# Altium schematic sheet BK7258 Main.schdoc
size 562 x 302 mm
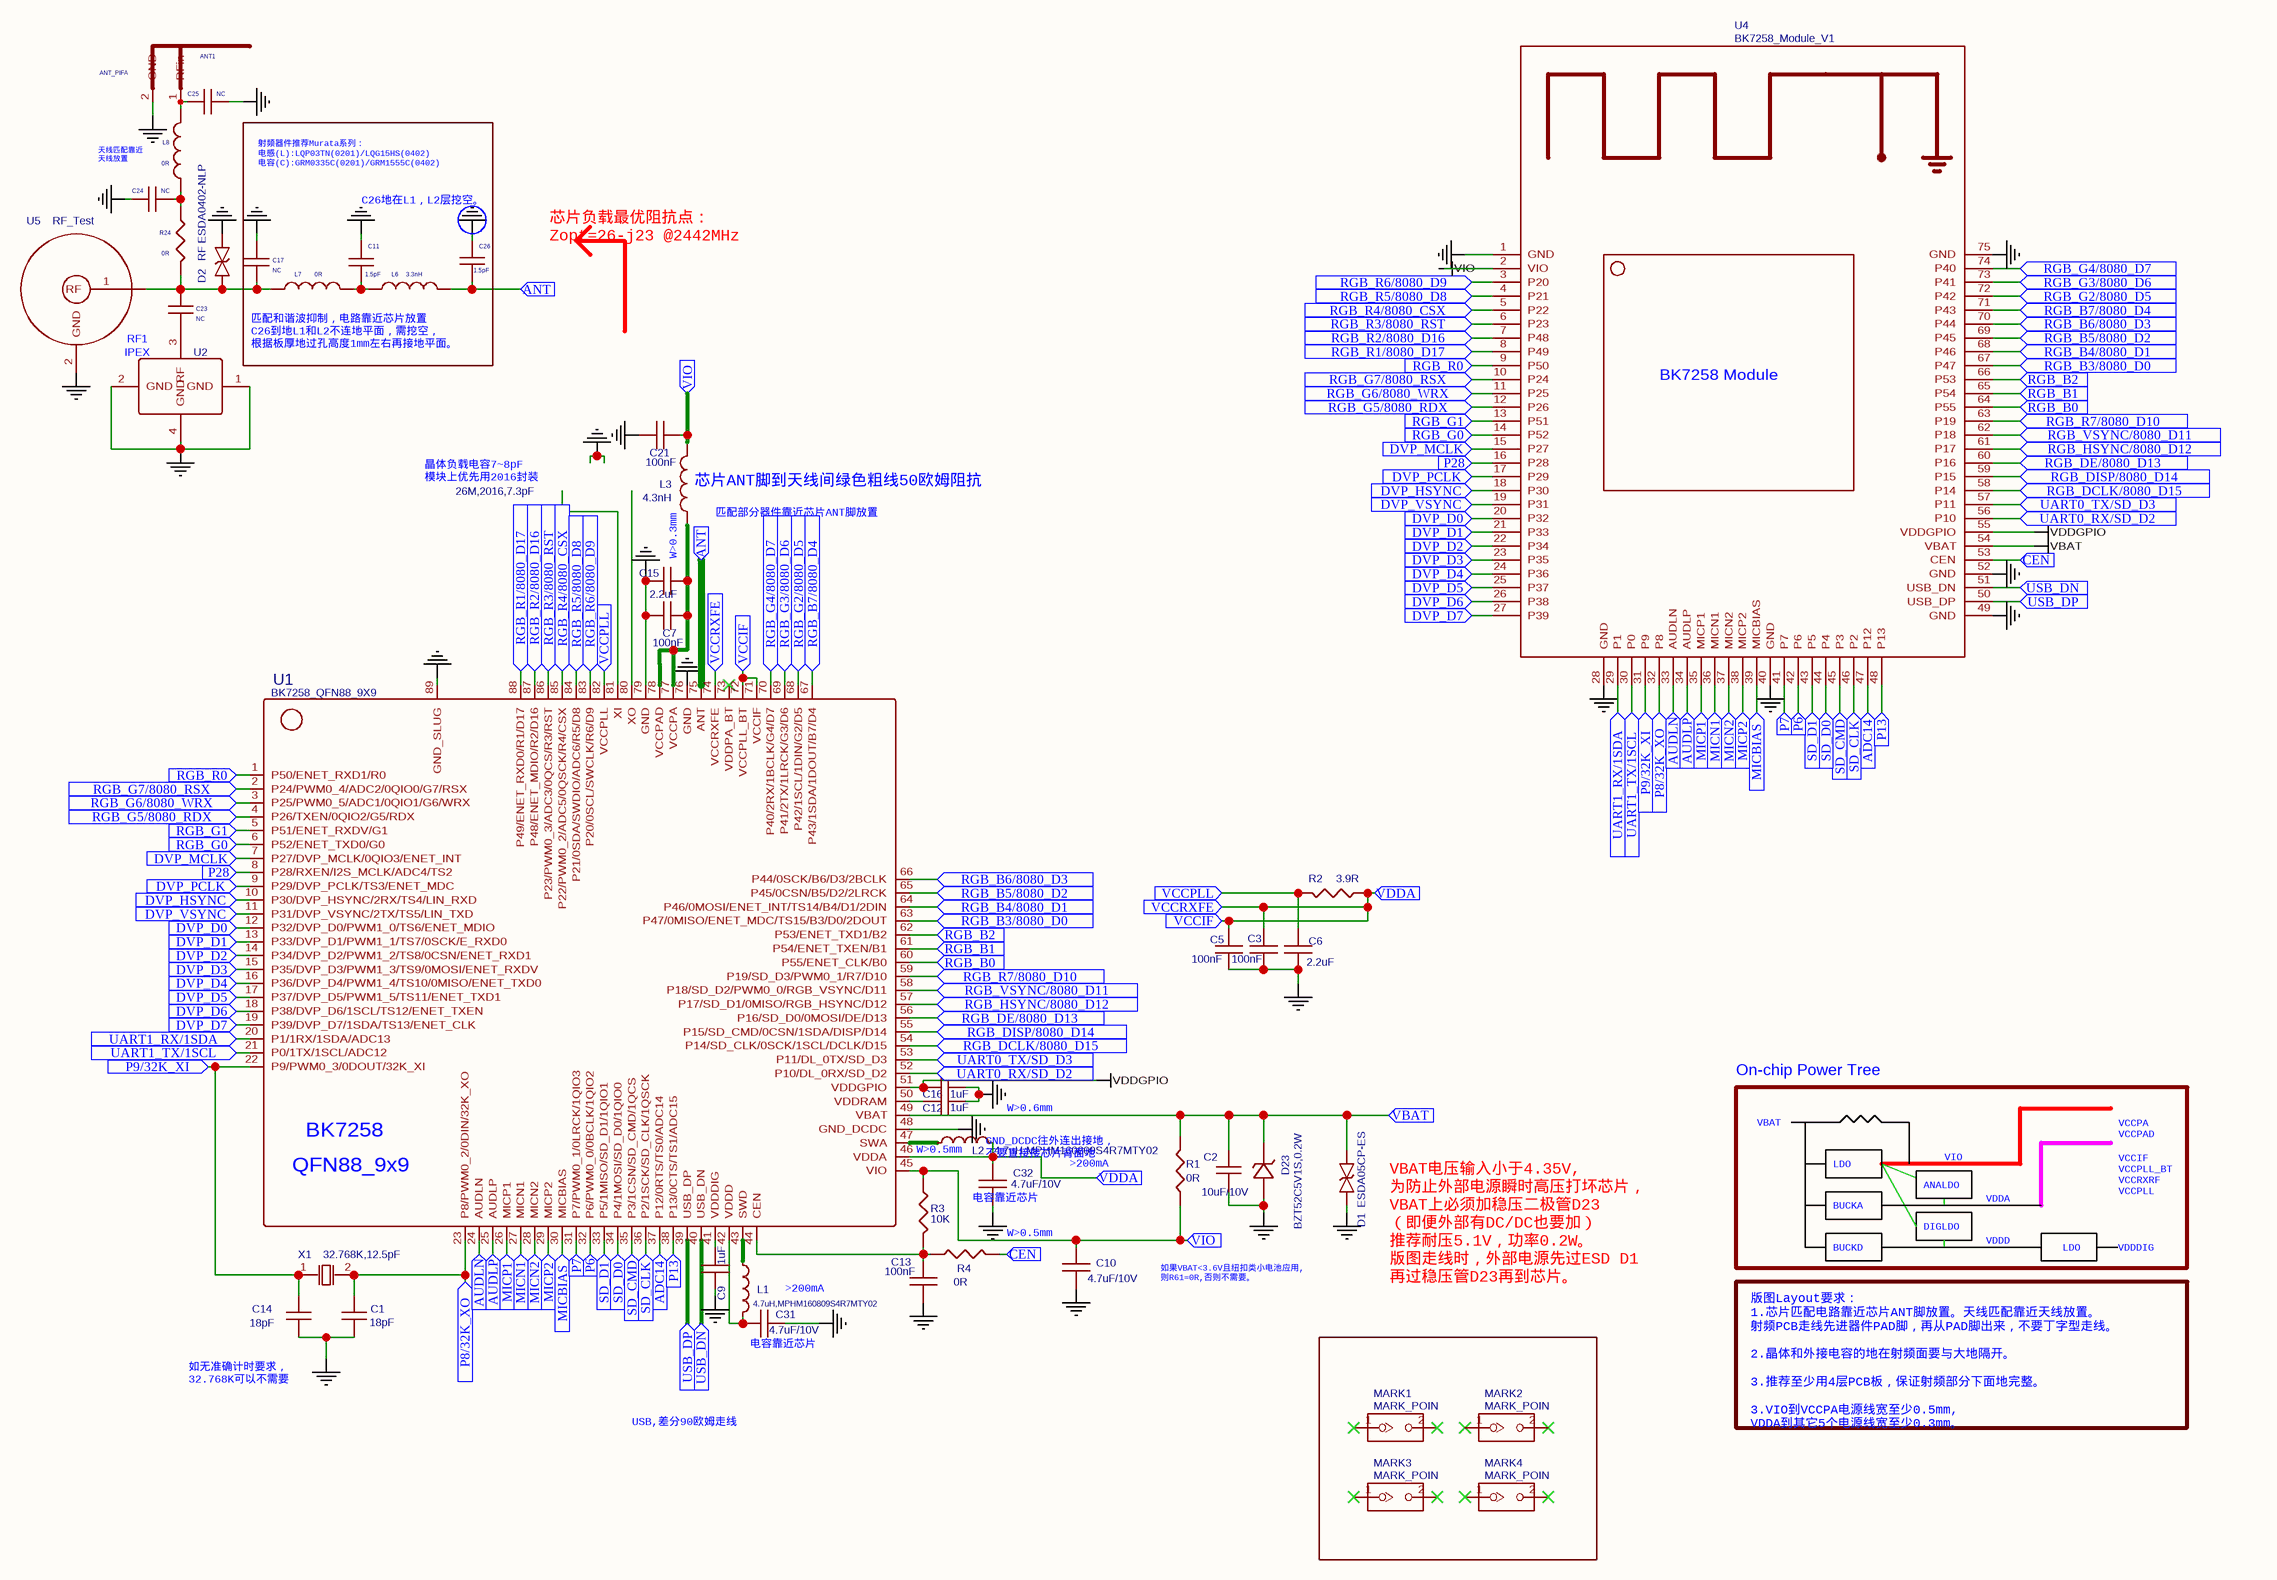
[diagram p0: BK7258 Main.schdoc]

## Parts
ANT1  ANT_PIFA  [ANT_F]
C1  18pF  [C0201]
C2  10uF/10V  [C0603]
C3  100nF  [C0402]
C5  100nF  [C0402]
C6  2.2uF  [C0402]
C7  100nF  [C0201]
C9  1uF  [C0402]
C10  4.7uF/10V  [C0603]
C11  1.5pF  [C0201]
C12  1uF  [C0402]
C13  100nF  [C0402]
C14  18pF  [C0201]
C15  2.2uF  [C0402]
C16  1uF  [C0402]
C17  NC  [C0201]
C21  100nF  [C0402]
C23  NC  [R0201]
C24  NC  [C0201]
C25  NC  [C0201]
C26  1.5pF  [C0201]
C31  4.7uF/10V  [C0603]
C32  4.7uF/10V  [C0603]
D1  ESDA05CP-ES  [ESD0402]
D2  RF ESDA0402-NLP  [ESD0402]
D23  BZT52C5V1S,0.2W  [SOD-323_L1.8-W1.3-LS2.5-RD]
L1  4.7uH,MPHM160809S4R7MTY02  [L0805]
L2  4.7uH,MPHM160809S4R7MTY02  [L0805]
L3  4.3nH  [L0402]
L6  3.3nH  [L0201]
L7  0R  [L0201]
L8  0R  [L0201]
MARK1  MARK_POIN  [MARK_POINT_V1]
MARK2  MARK_POIN  [MARK_POINT_V1]
MARK3  MARK_POIN  [MARK_POINT_V1]
MARK4  MARK_POIN  [MARK_POINT_V1]
R1  0R  [R0402]
R2  3.9R  [R0201]
R3  10K  [R0402]
R4  0R  [R0402]
R24  0R  [R0201]
U1  BK7258_QFN88_9X9  [QFN88_9X9_BK7258]
U2  IPEX  [20579-001E]  (value not drawn)
U4  BK7258_Module_V1  [BK7258_MODULE_V1]
U5  RF_Test  [RF_TP]
X1  32.768K,12.5pF  [3215]
X2  26M,2016,7.3pF  [3225_2016]

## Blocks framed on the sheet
C26地在L1，L2层挖空。: C11 C17 C26 L6 L7

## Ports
ADC14 (in), ANT (in), AUDLN (in), AUDLP (in), CEN (in), DVP_D0 (in), DVP_D1 (in), DVP_D2 (in), DVP_D3 (in), DVP_D4 (in), DVP_D5 (in), DVP_D6 (in), DVP_D7 (in), DVP_HSYNC (in), DVP_MCLK (in), DVP_PCLK (in), DVP_VSYNC (in), MICBIAS (in), MICN1 (in), MICN2 (in), MICP1 (in), MICP2 (in), P6 (in), P7 (in), P8/32K_XO (in), P9/32K_XI (in), P13 (in), P28 (in), RGB_B0 (in), RGB_B1 (in), RGB_B2 (in), RGB_B3/8080_D0 (in), RGB_B4/8080_D1 (in), RGB_B5/8080_D2 (in), RGB_B6/8080_D3 (in), RGB_B7/8080_D4 (in), RGB_DCLK/8080_D15 (in), RGB_DE/8080_D13 (in), RGB_DISP/8080_D14 (in), RGB_G0 (in), RGB_G1 (in), RGB_G2/8080_D5 (in), RGB_G3/8080_D6 (in), RGB_G4/8080_D7 (in), RGB_G5/8080_RDX (in), RGB_G6/8080_WRX (in), RGB_G7/8080_RSX (in), RGB_HSYNC/8080_D12 (in), RGB_R0 (in), RGB_R1/8080_D17 (in), RGB_R2/8080_D16 (in), RGB_R3/8080_RST (in), RGB_R4/8080_CSX (in), RGB_R5/8080_D8 (in), RGB_R6/8080_D9 (in), RGB_R7/8080_D10 (in), RGB_VSYNC/8080_D11 (in), SD_CLK (in), SD_CMD (in), SD_D0 (in), SD_D1 (in), UART0_RX/SD_D2 (in), UART0_TX/SD_D3 (in), UART1_RX/1SDA (in), UART1_TX/1SCL (in), USB_DN (in), USB_DP (in), VBAT (in), VCCIF (in), VCCPLL (in), VCCRXFE (in), VDDA (in), VIO (in)

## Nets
GGND: ANT1.2(GND) C1.2 C2.2 C3.1 C5.1 C6.1 C7.2 C9.1 C10.2 C11.2 C12.1 C13.2 C14.2 C15.2 C16.1 C17.2 C21.2 C24.1 C25.2 C26.1 C31.1 C32.2 D1.2 D2.1 D23.2(A) U1.48(GND_DCDC) U1.76(GND) U1.79(GND) U1.89(GND_SLUG) U2.1(GND) U2.2(GND) U2.4(GND) U4.1(GND) U4.28(GND) U4.40(GND) U4.49(GND) U4.52(GND) U4.75(GND) U5.2(GND)
VBAT: U4.54(VBAT)
VDDGPIO: C16.2 U1.51(VDDGPIO) U4.55(VDDGPIO)
ADC14: U1.37(P12/0RTS/TS0/ADC14) U4.47(P12) ; port ADC14
ANT: C26.2 L6.2 U1.75(ANT) ; port ANT
AUDLN: U1.24(AUDLN) U4.33(AUDLN) ; port AUDLN
AUDLP: U1.25(AUDLP) U4.34(AUDLP) ; port AUDLP
CEN: R4.1 U4.53(CEN) ; port CEN
DVP_D0: U1.12(P32/DVP_D0/PWM1_0/TS6/ENET_MDIO) U4.20(P32) ; port DVP_D0
DVP_D1: U1.13(P33/DVP_D1/PWM1_1/TS7/0SCK/E_RXD0) U4.21(P33) ; port DVP_D1
DVP_D2: U1.14(P34/DVP_D2/PWM1_2/TS8/0CSN/ENET_RXD1) U4.22(P34) ; port DVP_D2
DVP_D3: U1.15(P35/DVP_D3/PWM1_3/TS9/0MOSI/ENET_RXDV) U4.23(P35) ; port DVP_D3
DVP_D4: U1.16(P36/DVP_D4/PWM1_4/TS10/0MISO/ENET_TXD0) U4.24(P36) ; port DVP_D4
DVP_D5: U1.17(P37/DVP_D5/PWM1_5/TS11/ENET_TXD1) U4.25(P37) ; port DVP_D5
DVP_D6: U1.18(P38/DVP_D6/1SCL/TS12/ENET_TXEN) U4.26(P38) ; port DVP_D6
DVP_D7: U1.19(P39/DVP_D7/1SDA/TS13/ENET_CLK) U4.27(P39) ; port DVP_D7
DVP_HSYNC: U1.10(P30/DVP_HSYNC/2RX/TS4/LIN_RXD) U4.18(P30) ; port DVP_HSYNC
DVP_MCLK: U1.7(P27/DVP_MCLK/0QIO3/ENET_INT) U4.15(P27) ; port DVP_MCLK
DVP_PCLK: U1.9(P29/DVP_PCLK/TS3/ENET_MDC) U4.17(P29) ; port DVP_PCLK
DVP_VSYNC: U1.11(P31/DVP_VSYNC/2TX/TS5/LIN_TXD) U4.19(P31) ; port DVP_VSYNC
MICBIAS: U1.30(MICBIAS) U4.39(MICBIAS) ; port MICBIAS
MICN1: U1.27(MICN1) U4.36(MICN1) ; port MICN1
MICN2: U1.28(MICN2) U4.37(MICN2) ; port MICN2
MICP1: U1.26(MICP1) U4.35(MICP1) ; port MICP1
MICP2: U1.29(MICP2) U4.38(MICP2) ; port MICP2
P6: U1.32(P6/PWM0_0/0BCLK/1QIO2) U4.42(P6) ; port P6
P7: U1.31(P7/PWM0_1/0LRCK/1QIO3) U4.41(P7) ; port P7
P8/32K_XO: C1.1 U1.23(P8/PWM0_2/0DIN/32K_XO) U4.32(P8) X1.2(OSC2) ; port P8/32K_XO
P9/32K_XI: C14.1 U1.22(P9/PWM0_3/0DOUT/32K_XI) U4.31(P9) X1.1(OSC1) ; port P9/32K_XI
P13: U1.38(P13/0CTS/TS1/ADC15) U4.48(P13) ; port P13
P28: U1.8(P28/RXEN/I2S_MCLK/ADC4/TS2) U4.16(P28) ; port P28
RGB_B0: U1.60(P55/ENET_CLK/B0) U4.64(P55) ; port RGB_B0
RGB_B1: U1.61(P54/ENET_TXEN/B1) U4.65(P54) ; port RGB_B1
RGB_B2: U1.62(P53/ENET_TXD1/B2) U4.66(P53) ; port RGB_B2
RGB_B3/8080_D0: U1.63(P47/0MISO/ENET_MDC/TS15/B3/D0/2DOUT) U4.67(P47) ; port RGB_B3/8080_D0
RGB_B4/8080_D1: U1.64(P46/0MOSI/ENET_INT/TS14/B4/D1/2DIN) U4.68(P46) ; port RGB_B4/8080_D1
RGB_B5/8080_D2: U1.65(P45/0CSN/B5/D2/2LRCK) U4.69(P45) ; port RGB_B5/8080_D2
RGB_B6/8080_D3: U1.66(P44/0SCK/B6/D3/2BCLK) U4.70(P44) ; port RGB_B6/8080_D3
RGB_B7/8080_D4: U1.67(P43/1SDA/1DOUT/B7/D4) U4.71(P43) ; port RGB_B7/8080_D4
RGB_DCLK/8080_D15: U1.54(P14/SD_CLK/0SCK/1SCL/DCLK/D15) U4.58(P14) ; port RGB_DCLK/8080_D15
RGB_DE/8080_D13: U1.56(P16/SD_D0/0MOSI/DE/D13) U4.60(P16) ; port RGB_DE/8080_D13
RGB_DISP/8080_D14: U1.55(P15/SD_CMD/0CSN/1SDA/DISP/D14) U4.59(P15) ; port RGB_DISP/8080_D14
RGB_G0: U1.6(P52/ENET_TXD0/G0) U4.14(P52) ; port RGB_G0
RGB_G1: U1.5(P51/ENET_RXDV/G1) U4.13(P51) ; port RGB_G1
RGB_G2/8080_D5: U1.68(P42/1SCL/1DIN/G2/D5) U4.72(P42) ; port RGB_G2/8080_D5
RGB_G3/8080_D6: U1.69(P41/2TX/1LRCK/G3/D6) U4.73(P41) ; port RGB_G3/8080_D6
RGB_G4/8080_D7: U1.70(P40/2RX/1BCLK/G4/D7) U4.74(P40) ; port RGB_G4/8080_D7
RGB_G5/8080_RDX: U1.4(P26/TXEN/0QIO2/G5/RDX) U4.12(P26) ; port RGB_G5/8080_RDX
RGB_G6/8080_WRX: U1.3(P25/PWM0_5/ADC1/0QIO1/G6/WRX) U4.11(P25) ; port RGB_G6/8080_WRX
RGB_G7/8080_RSX: U1.2(P24/PWM0_4/ADC2/0QIO0/G7/RSX) U4.10(P24) ; port RGB_G7/8080_RSX
RGB_HSYNC/8080_D12: U1.57(P17/SD_D1/0MISO/RGB_HSYNC/D12) U4.61(P17) ; port RGB_HSYNC/8080_D12
RGB_R0: U1.1(P50/ENET_RXD1/R0) U4.9(P50) ; port RGB_R0
RGB_R1/8080_D17: U1.88(P49/ENET_RXD0/R1/D17) U4.8(P49) ; port RGB_R1/8080_D17
RGB_R2/8080_D16: U1.87(P48/ENET_MDIO/R2/D16) U4.7(P48) ; port RGB_R2/8080_D16
RGB_R3/8080_RST: U1.86(P23/PWM0_3/ADC3/0QCS/R3/RST) U4.6(P23) ; port RGB_R3/8080_RST
RGB_R4/8080_CSX: U1.81(XI) U1.85(P22/PWM0_2/ADC5/0QSCK/R4/CSX) U4.5(P22) ; port RGB_R4/8080_CSX
RGB_R5/8080_D8: U1.84(P21/0SDA/SWDIO/ADC6/R5/D8) U4.4(P21) ; port RGB_R5/8080_D8
RGB_R6/8080_D9: U1.83(P20/0SCL/SWCLK/R6/D9) U4.3(P20) ; port RGB_R6/8080_D9
RGB_R7/8080_D10: U1.59(P19/SD_D3/PWM0_1/R7/D10) U4.63(P19) ; port RGB_R7/8080_D10
RGB_VSYNC/8080_D11: U1.58(P18/SD_D2/PWM0_0/RGB_VSYNC/D11) U4.62(P18) ; port RGB_VSYNC/8080_D11
SD_CLK: U1.36(P2/1SCK/SD_CLK/1QSCK) U4.46(P2) ; port SD_CLK
SD_CMD: U1.35(P3/1CSN/SD_CMD/1QCS) U4.45(P3) ; port SD_CMD
SD_D0: U1.34(P4/1MOSI/SD_D0/1QIO0) U4.44(P4) ; port SD_D0
SD_D1: U1.33(P5/1MISO/SD_D1/1QIO1) U4.43(P5) ; port SD_D1
UART0_RX/SD_D2: U1.52(P10/DL_0RX/SD_D2) U4.56(P10) ; port UART0_RX/SD_D2
UART0_TX/SD_D3: U1.53(P11/DL_0TX/SD_D3) U4.57(P11) ; port UART0_TX/SD_D3
UART1_RX/1SDA: U1.20(P1/1RX/1SDA/ADC13) U4.29(P1) ; port UART1_RX/1SDA
UART1_TX/1SCL: U1.21(P0/1TX/1SCL/ADC12) U4.30(P0) ; port UART1_TX/1SCL
USB_DN: U1.40(USB_DN) U4.51(USB_DN) ; port USB_DN
USB_DP: U1.39(USB_DP) U4.50(USB_DP) ; port USB_DP
VBAT: C2.1 D1.1 D23.1(K) R1.1 U1.49(VBAT) ; port VBAT  [a separate net that carries the same name]
VCCIF: C3.2 C5.2 C32.1 L2.2 R2.1 U1.46(VDDA) U1.71(VCCIF) U1.72(VCCPLL_BT) U1.74(VCCRXFE) ; port VDDA, port VCCRXFE, port VCCIF
VCCPLL: C6.2 R2.2 U1.82(VCCPLL) ; port VCCPLL
VIO: C10.1 C21.1 L3.2 R1.2 R3.2 U1.45(VIO) ; port VIO
NetANT1_1: ANT1.1(RFin) C25.1 L8.2
NetC7_1: C7.1 C15.1 L3.1 U1.77(VCCPA) U1.78(VCCPAD)
NetC9_2: C9.2 U1.41(VDDDIG)
NetC11_1: C11.1 L6.1 L7.2
NetC12_2: C12.2 U1.50(VDDRAM)
NetC13_1: C13.1 R3.1 R4.2 U1.44(CEN)
NetC17_1: C17.1 C23.1 D2.2 L7.1 R24.1 U5.1(RF)
NetC23_2: C23.2 U2.3(RF)
NetC24_2: C24.2 L8.1 R24.2
NetC31_2: C31.2 L1.2 U1.42(VDDD)
NetL1_1: L1.1 U1.43(SWD)
NetL2_1: L2.1 U1.47(SWA)

Not connected (* = marked no-connect by the designer): MARK1 1* 2*; MARK2 1* 2*; MARK3 1* 2*; MARK4 1* 2*; U1 73(VDDPA_BT)* 80(XO); U4 2(VIO)

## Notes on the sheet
- 天线匹配靠近
  天线放置
- 射频器件推荐Murata系列：
  电感(L):LQP03TN(0201)/LQG15HS(0402)
  电容(C):GRM0335C(0201)/GRM1555C(0402)
- 芯片负载最优阻抗点：
  Zopt=26-j23 @2442MHz
- 匹配和谐波抑制，电路靠近芯片放置
  C26到地L1和L2不连地平面，需挖空，
  根据板厚地过孔高度1mm左右再接地平面。
- (near X2) 晶体负载电容7~8pF
  模块上优先用2016封装
- (near L3) 芯片ANT脚到天线间绿色粗线50欧姆阻抗
- (near L3) 匹配部分器件靠近芯片ANT脚放置
- (near L3) W>0.3mm
- On-chip Power Tree
- (near L2) W>0.5mm
- GND_DCDC往外连出接地，
  不要直接接芯片背面地
- (near L2) W>0.6mm
- (near D1) VBAT电压输入小于4.35V,
  为防止外部电源瞬时高压打坏芯片，
  VBAT上必须加稳压二极管D23
  （即便外部有DC/DC也要加）
  推荐耐压5.1V，功率0.2W。
  版图走线时，外部电源先过ESD D1
  再过稳压管D23再到芯片。
- VBAT
- VCCIF
  VCCPLL_BT
  VCCRXRF
  VCCPLL
- VCCPA
  VCCPAD
- (near C32) 电容靠近芯片
- >200mA
- BUCKA
- LDO
- DIGLDO
- ANALDO
- VIO
- VDDA
- W>0.5mm
- 如果VBAT<3.6V且纽扣类小电池应用,
  则R61=0R,否则不需要。
- 版图Layout要求：
  1.芯片匹配电路靠近芯片ANT脚放置。天线匹配靠近天线放置。
  射频PCB走线先进器件PAD脚，再从PAD脚出来，不要丁字型走线。
  2.晶体和外接电容的地在射频面要与大地隔开。
  3.推荐至少用4层PCB板，保证射频部分下面地完整。
  3.VIO到VCCPA电源线宽至少0.5mm,
  VDDA到其它5个电源线宽至少0.3mm。
- BUCKD
- VDDD
- VDDDIG
- 如无准确计时要求，
  32.768K可以不需要
- (near C31) 电容靠近芯片
- USB,差分90欧姆走线
- Labels drawn without touching a wire or pin: VIO

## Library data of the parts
ANT1 = ANT_PIFA: Package Display: No
C1 C14 = 18pF: Manufacturer Part Number: 06035A101KAT2A; Manufacturer: AVX; APN: C029-0
C2 = 10uF/10V: Manufacturer Part Number: 06035A101KAT2A; Manufacturer: AVX; APN: C029-0
C3 C5 C7 C13 C21 = 100nF: Manufacturer Part Number: 0805ZC105KAT2A; Manufacturer: AVX; APN: C071-0
C6 C15 = 2.2uF: Manufacturer Part Number: 0805ZC105KAT2A; Manufacturer: AVX; APN: C071-0
C9 C12 C16 = 1uF: Manufacturer Part Number: 0805ZC105KAT2A; Manufacturer: AVX; APN: C071-0
C10 C31 C32 = 4.7uF/10V: Manufacturer Part Number: 0805ZC105KAT2A; Manufacturer: AVX; APN: C071-0
C11 C26 = 1.5pF: Manufacturer Part Number: 06035A101KAT2A; Manufacturer: AVX; APN: C029-0
C17 C23-C25 = NC: Manufacturer Part Number: 06035A101KAT2A; Manufacturer: AVX; APN: C029-0
D1 = ESDA05CP-ES: Contributor: D-MAN
D2 = RF ESDA0402-NLP: Contributor: D-MAN
D23 = BZT52C5V1S,0.2W: Manufacturer: GOODWORK; Contributor: LCSC
L1 = 4.7uH,MPHM160809S4R7MTY02: Manufacturer: Sunlord(顺络); Manufacturer Part: MPH201210S4R7MT; nameAlias: Value; Contributor: lcsc; 3DModel: L0805_L2.0-W1.6-H0.9
L2 = 4.7uH,MPHM160809S4R7MTY02: Manufacturer: Sunlord(顺络); Manufacturer Part: MPH201214S4R7MT; nameAlias: Value; Contributor: LCSC
L3 = 4.3nH: Manufacturer: COILCRAFT; Manufacturer Part Number: 1008HT-R27TJBC; APN: L914-0
L6 = 3.3nH: Manufacturer: COILCRAFT; Manufacturer Part Number: 1008HT-R27TJBC; APN: L914-0
L7 L8 = 0R: Manufacturer: COILCRAFT; Manufacturer Part Number: 1008HT-R27TJBC; APN: L914-0
MARK1-MARK4 = MARK_POIN: Contributor: guogen.le
R1 R4 R24 = 0R: Manufacturer Part Number: RM73B1JT240J; Manufacturer: KOA; APN: R125-0
R2 = 3.9R: Manufacturer Part Number: RM73B1JT240J; Manufacturer: KOA; APN: R125-0
R3 = 10K: Manufacturer Part Number: RM73B1JT240J; Manufacturer: KOA; APN: R125-0
U1 = BK7258_QFN88_9X9: Contributor: qunshan.xu
U2 = IPEX: Contributor: jian.shi1
U4 = BK7258_Module_V1: Contributor: guogen.le
U5 = RF_Test: Contributor: jian.shi1
X1 = 32.768K,12.5pF: BOM_Manufacturer: YXC; BOM_Manufacturer Part: X49SM1431818MSD2SC; nameAlias: Frequency
X2 = 26M,2016,7.3pF: BOM_Manufacturer: JWT; Manufacturer Part: CF4026M000739FA40000; Contributor: qunshan.xu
